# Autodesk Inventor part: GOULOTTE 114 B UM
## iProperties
Shininess: 25.0
Length Units: 11269
Angle Units: 11279
Time Units: 11290
Mass Units: 11283
Length Display Precision: 3
Angle Display Precision: 2
Created: 2001-02
Part Number: GOULOTTE 114 B UM
Material: Par défaut
Document SubType Name: Tôlerie
Designer: Administrateur
Density: 0.0
Volumn: 0.0
Area: 0.0
PropertySet Name: Model Information
Control State: 0
Master: False
Checked Out: False
Author: Administrateur
